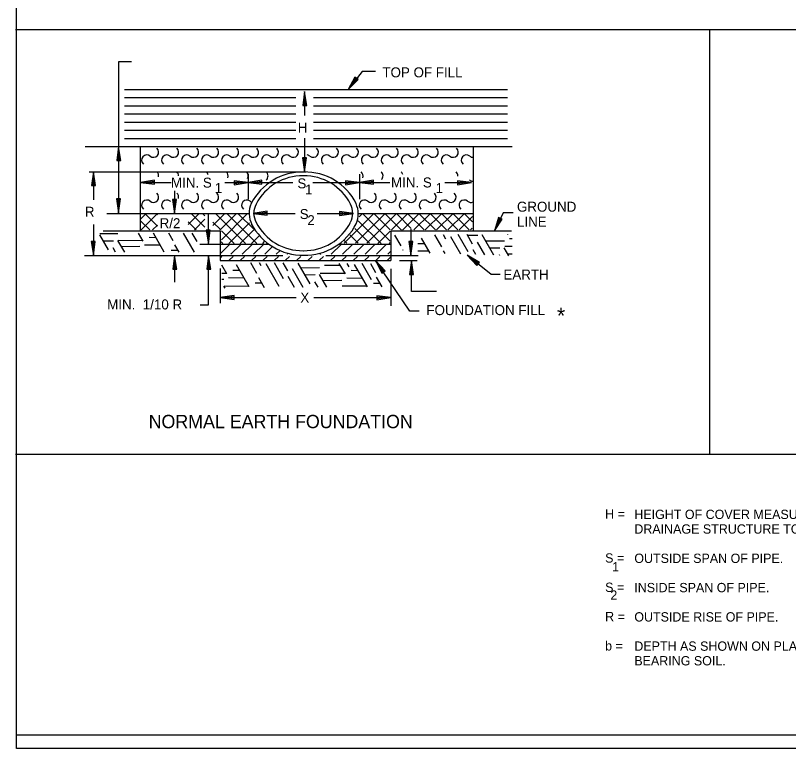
# Model space of a CAD drawing. Extents: x 0 to 390, y 0 to 265.
# Drawn here: x -0.2 to 144.9, y 0 to 137.7 of the extents above; entities that cross this region are included whole.
import ezdxf

# ---------------------------------------------------------------- set-up
doc = ezdxf.new("R2010")
doc.units = 0
doc.layers.add('D_Details', color=7, linetype='Continuous')
doc.layers.add('Default', color=7, linetype='Continuous')

msp = doc.modelspace()

# ---------------------------------------------------------------- linework, layer by layer
at = {"layer": 'D_Details'}
for p, q in [((-0.22, 135.01), (388.66, 135.01)), ((130.04, 135.01), (130.04, 55.26)), ((21.55, 128.98), (19.13, 128.98)), ((19.13, 128.98), (19.13, 113.05)), ((64.85, 127.14), (62.23, 123.76)), ((67.36, 127.14), (64.85, 127.14)), ((63.51, 126.09), (62.23, 123.76)), ((62.23, 123.76), (64.1, 125.63)), ((62.63, 124.28), (63.66, 125.97)), ((63.95, 125.74), (62.63, 124.28)), ((63.25, 125.11), (63.73, 125.92)), ((63.88, 125.8), (63.25, 125.11)), ((64.1, 125.63), (63.51, 126.09)), ((20.23, 123.76), (92.15, 123.76)), ((54.05, 123.38), (53.71, 120.75)), ((54.46, 120.75), (54.05, 123.38)), ((54.05, 123.38), (54.05, 118.89)), ((20.23, 122.23), (52.42, 122.23)), ((53.9, 120.75), (54.05, 122.72)), ((54.05, 122.72), (54.27, 120.75)), ((55.72, 122.23), (92.15, 122.23)), ((20.23, 120.7), (52.42, 120.7)), ((53.71, 120.75), (54.46, 120.75)), ((53.99, 120.75), (54.07, 121.69)), ((54.07, 121.69), (54.18, 120.75)), ((55.72, 120.7), (92.15, 120.7)), ((20.23, 119.17), (52.42, 119.17)), ((55.72, 119.17), (92.15, 119.17)), ((20.23, 117.64), (52.42, 117.64)), ((55.72, 117.64), (92.15, 117.64)), ((20.23, 116.11), (52.42, 116.11)), ((55.72, 116.11), (92.15, 116.11)), ((20.23, 114.58), (52.42, 114.58)), ((54.05, 114.59), (54.05, 108.32)), ((55.72, 114.58), (92.15, 114.58)), ((12.87, 113.05), (93.01, 113.05)), ((19.14, 113.05), (18.8, 110.43)), ((18.99, 110.43), (19.14, 112.39)), ((19.13, 113.05), (19.13, 100.6)), ((19.55, 110.43), (19.14, 113.05)), ((19.14, 112.39), (19.36, 110.43)), ((23.19, 112.95), (23.19, 97.22)), ((85.68, 112.86), (85.68, 97.22)), ((18.8, 110.43), (19.55, 110.43)), ((19.08, 110.43), (19.15, 111.36)), ((19.15, 111.36), (19.27, 110.43)), ((54.39, 110.94), (53.64, 110.94)), ((53.64, 110.94), (54.05, 108.32)), ((54.05, 108.98), (53.82, 110.94)), ((54.03, 110.01), (53.92, 110.94)), ((54.1, 110.94), (54.03, 110.01)), ((54.05, 108.32), (54.39, 110.94)), ((54.2, 110.94), (54.05, 108.98)), ((13.64, 108.32), (54.34, 108.32)), ((14.41, 108.32), (14.07, 105.7)), ((14.26, 105.7), (14.41, 107.66)), ((14.82, 105.7), (14.41, 108.32)), ((14.41, 108.32), (14.41, 103.03)), ((14.41, 107.66), (14.63, 105.7)), ((43.44, 107.93), (43.44, 103.16)), ((64.37, 107.84), (64.37, 103.16)), ((14.35, 105.7), (14.43, 106.63)), ((14.43, 106.63), (14.54, 105.7)), ((25.91, 106.71), (23.28, 106.29)), ((23.28, 106.29), (25.91, 105.96)), ((23.28, 106.29), (29, 106.29)), ((23.94, 106.29), (25.91, 106.52)), ((25.91, 106.14), (23.94, 106.29)), ((24.97, 106.31), (25.91, 106.42)), ((25.91, 106.24), (24.97, 106.31)), ((25.91, 105.96), (25.91, 106.71)), ((39.07, 106.29), (43.44, 106.29)), ((43.44, 106.29), (40.82, 106.63)), ((40.82, 106.63), (40.82, 105.88)), ((40.82, 106.44), (42.78, 106.29)), ((40.82, 106.35), (41.75, 106.27)), ((40.82, 105.88), (43.44, 106.29)), ((42.78, 106.29), (40.82, 106.07)), ((41.75, 106.27), (40.82, 106.16)), ((46.06, 106.71), (43.44, 106.29)), ((43.44, 106.29), (46.06, 105.96)), ((43.44, 106.29), (51.84, 106.29)), ((44.1, 106.29), (46.06, 106.52)), ((46.06, 106.14), (44.1, 106.29)), ((45.13, 106.31), (46.06, 106.42)), ((46.06, 106.24), (45.13, 106.31)), ((46.06, 105.96), (46.06, 106.71)), ((55.58, 106.29), (64.37, 106.29)), ((64.37, 106.29), (61.74, 106.63)), ((61.74, 106.63), (61.74, 105.88)), ((61.74, 106.44), (63.71, 106.29)), ((61.74, 106.35), (62.68, 106.27)), ((61.74, 105.88), (64.37, 106.29)), ((63.71, 106.29), (61.74, 106.07)), ((62.68, 106.27), (61.74, 106.16)), ((66.99, 106.71), (64.37, 106.29)), ((64.37, 106.29), (66.99, 105.96)), ((64.37, 106.29), (70.04, 106.29)), ((65.02, 106.29), (66.99, 106.52)), ((66.99, 106.14), (65.02, 106.29)), ((66.06, 106.31), (66.99, 106.42)), ((66.99, 106.24), (66.06, 106.31)), ((66.99, 105.96), (66.99, 106.71)), ((80.36, 106.29), (85.39, 106.29)), ((85.39, 106.29), (82.77, 106.63)), ((82.77, 106.63), (82.77, 105.88)), ((82.77, 106.44), (84.74, 106.29)), ((82.77, 106.35), (83.71, 106.27)), ((82.77, 105.88), (85.39, 106.29)), ((84.74, 106.29), (82.77, 106.07)), ((83.71, 106.27), (82.77, 106.16)), ((14.07, 105.7), (14.82, 105.7)), ((29.65, 104.75), (29.65, 100.5)), ((19.47, 103.22), (18.72, 103.22)), ((18.72, 103.22), (19.14, 100.6)), ((19.14, 101.25), (18.91, 103.22)), ((19.12, 102.29), (19, 103.22)), ((19.19, 103.22), (19.12, 102.29)), ((19.14, 100.6), (19.47, 103.22)), ((19.29, 103.22), (19.14, 101.25)), ((29.99, 103.13), (29.24, 103.13)), ((29.24, 103.13), (29.65, 100.5)), ((29.65, 101.16), (29.42, 103.13)), ((29.63, 102.19), (29.52, 103.13)), ((29.7, 103.13), (29.63, 102.19)), ((29.65, 100.5), (29.99, 103.13)), ((29.8, 103.13), (29.65, 101.16)), ((16.92, 100.5), (43.65, 100.5)), ((23.28, 99.4), (24.27, 100.39)), ((23.39, 97.38), (26.35, 100.35)), ((26.43, 98.08), (24.12, 100.39)), ((26.43, 100.2), (26.29, 100.35)), ((32.23, 98.41), (34.17, 100.35)), ((35.32, 97.92), (32.89, 100.35)), ((35.32, 100.04), (35.01, 100.35)), ((36.01, 94.71), (36.01, 100.5)), ((36.83, 98.19), (39.02, 100.39)), ((36.87, 100.35), (36.92, 100.41)), ((42.96, 94.85), (37.4, 100.4)), ((38.13, 97.37), (41.13, 100.37)), ((38.43, 95.55), (43.23, 100.35)), ((45.08, 94.85), (39.54, 100.38)), ((44.45, 97.6), (41.68, 100.36)), ((47.06, 100.91), (44.43, 100.5)), ((44.43, 100.5), (52.27, 100.5)), ((44.43, 100.5), (47.06, 100.16)), ((45.09, 100.5), (47.06, 100.73)), ((47.06, 100.35), (45.09, 100.5)), ((46.12, 100.52), (47.06, 100.63)), ((47.06, 100.45), (46.12, 100.52)), ((47.06, 100.16), (47.06, 100.91)), ((56.44, 100.5), (63.21, 100.5)), ((63.21, 100.5), (60.58, 100.84)), ((60.58, 100.84), (60.58, 100.09)), ((60.58, 100.65), (62.55, 100.5)), ((60.58, 100.56), (61.52, 100.48)), ((60.58, 100.09), (63.21, 100.5)), ((62.55, 100.5), (60.58, 100.28)), ((61.52, 100.48), (60.58, 100.37)), ((61.51, 94.91), (67.01, 100.41)), ((63.62, 94.89), (69.13, 100.41)), ((64.14, 100.5), (85.68, 100.5)), ((64.33, 99.85), (64.89, 100.41)), ((70.1, 95.28), (64.97, 100.41)), ((65.72, 94.88), (71.25, 100.41)), ((70.1, 97.4), (67.09, 100.41)), ((72.25, 97.37), (69.21, 100.41)), ((70.4, 97.43), (73.37, 100.41)), ((74.08, 97.66), (71.34, 100.41)), ((72.45, 97.37), (75.49, 100.41)), ((76.48, 97.38), (73.46, 100.41)), ((74.59, 97.38), (77.62, 100.41)), ((78.6, 97.38), (75.58, 100.41)), ((76.71, 97.38), (79.74, 100.41)), ((80.72, 97.38), (77.7, 100.41)), ((78.83, 97.38), (81.86, 100.41)), ((82.84, 97.38), (79.82, 100.41)), ((80.95, 97.38), (83.98, 100.41)), ((84.97, 97.38), (81.94, 100.41)), ((85.56, 98.91), (84.06, 100.41)), ((91.36, 100.59), (89.68, 97.22)), ((93.23, 100.59), (91.36, 100.59)), ((25.01, 97.38), (23.28, 99.11)), ((33.7, 97.41), (32.23, 98.88)), ((33.36, 97.42), (35.32, 99.38)), ((38.31, 97.38), (36.84, 98.85)), ((39.85, 94.85), (43.71, 98.71)), ((68.4, 94.86), (64.14, 99.12)), ((83.07, 97.38), (85.58, 99.89)), ((90.48, 99.75), (89.68, 97.22)), ((89.68, 97.22), (91.15, 99.42)), ((89.97, 97.81), (90.65, 99.67)), ((90.98, 99.5), (89.97, 97.81)), ((90.41, 98.74), (90.73, 99.63)), ((90.9, 99.54), (90.41, 98.74)), ((91.15, 99.42), (90.48, 99.75)), ((14.41, 98.43), (14.41, 92.61)), ((25.51, 97.38), (26.43, 98.31)), ((36.35, 97.34), (35.6, 97.34)), ((35.6, 97.34), (36.01, 94.71)), ((36.35, 97.34), (35.6, 97.34)), ((35.6, 97.34), (36.01, 94.71)), ((36.01, 95.37), (35.79, 97.34)), ((36.01, 95.37), (35.79, 97.34)), ((35.99, 96.4), (35.88, 97.34)), ((35.99, 96.4), (35.88, 97.34)), ((36.07, 97.34), (35.99, 96.4)), ((36.07, 97.34), (35.99, 96.4)), ((36.01, 94.71), (36.35, 97.34)), ((36.16, 97.34), (36.01, 95.37)), ((36.01, 94.71), (36.35, 97.34)), ((36.16, 97.34), (36.01, 95.37)), ((41.97, 94.85), (44.56, 97.44)), ((66.26, 94.87), (63.49, 97.65)), ((74.01, 97.51), (74.01, 92.61)), ((74.36, 97.38), (74.36, 97.39)), ((85.19, 97.38), (85.54, 97.72)), ((18.97, 96.66), (15.63, 96.65)), ((17.25, 93.67), (15.65, 96.44)), ((16.24, 97.22), (38.23, 97.22)), ((23.74, 95.29), (22.9, 96.75)), ((26.16, 95.93), (24.87, 95.94)), ((27.72, 93.21), (25.68, 96.75)), ((29.37, 95.35), (28.56, 96.75)), ((33.38, 93.21), (31.35, 96.75)), ((33.87, 95.2), (32.98, 96.75)), ((38.23, 97.22), (38.23, 91.62)), ((40.84, 94.85), (38.47, 97.21)), ((44.09, 94.85), (45.48, 96.24)), ((64.13, 94.89), (62.55, 96.47)), ((67.83, 94.86), (70.1, 97.13)), ((70.25, 97.22), (70.25, 91.62)), ((70.25, 97.22), (92.92, 97.22)), ((72.16, 94.43), (71.02, 96.4)), ((77.6, 93.02), (75.98, 95.83)), ((79.8, 94.2), (78.51, 96.45)), ((80.59, 95.65), (80.13, 96.47)), ((83.37, 92.84), (81.5, 96.08)), ((84.76, 93.25), (82.9, 96.5)), ((85.6, 94.71), (84.55, 96.53)), ((86.56, 96.36), (84.73, 96.34)), ((89.58, 92.64), (87.37, 96.46)), ((92.23, 96.55), (92.19, 96.62)), ((14.75, 95.24), (14, 95.24)), ((14, 95.24), (14.41, 92.61)), ((14.41, 93.27), (14.18, 95.24)), ((14.39, 94.3), (14.28, 95.24)), ((14.47, 95.24), (14.39, 94.3)), ((14.41, 92.61), (14.75, 95.24)), ((14.56, 95.24), (14.41, 93.27)), ((18.19, 95.3), (16.32, 95.29)), ((20.29, 93.21), (19.01, 95.42)), ((23.69, 95.36), (19.04, 95.41)), ((26.9, 94.51), (24.01, 94.53)), ((30.5, 93.21), (29.72, 94.57)), ((34.37, 94.71), (47.29, 94.71)), ((38.27, 92.98), (39.95, 94.66)), ((38.71, 94.85), (38.42, 95.14)), ((40.22, 92.81), (42.08, 94.67)), ((42.34, 92.81), (44.2, 94.67)), ((44.46, 92.81), (46.33, 94.68)), ((46.21, 94.85), (46.55, 95.19)), ((59.06, 92.81), (60.93, 94.67)), ((60.48, 94.71), (70.25, 94.71)), ((61.18, 92.81), (63.04, 94.66)), ((61.99, 94.9), (61.47, 95.43)), ((63.3, 92.81), (65.15, 94.65)), ((65.43, 92.81), (67.26, 94.64)), ((67.55, 92.81), (69.37, 94.63)), ((69.94, 94.85), (70.1, 95.01)), ((74.35, 95.24), (73.6, 95.24)), ((73.6, 95.24), (74.01, 92.61)), ((74.01, 93.27), (73.79, 95.24)), ((73.99, 94.3), (73.88, 95.24)), ((74.07, 95.24), (73.99, 94.3)), ((74.01, 92.61), (74.35, 95.24)), ((74.16, 95.24), (74.01, 93.27)), ((76.59, 94.79), (75.3, 94.8)), ((87.87, 92.69), (86.5, 95.1)), ((91.55, 95.3), (88.1, 95.26)), ((93.04, 95.74), (92.51, 95.74)), ((18.56, 93.21), (18.1, 94)), ((23.14, 94.25), (19.71, 94.24)), ((30.32, 93.53), (29.03, 93.54)), ((46.58, 92.81), (47.98, 94.21)), ((48.7, 92.81), (49.38, 93.49)), ((50.82, 92.81), (50.94, 92.93)), ((56.94, 92.81), (57.1, 92.97)), ((69.67, 92.81), (70.19, 93.34)), ((72.58, 93.53), (72.5, 93.66)), ((77.33, 93.37), (75.32, 93.38)), ((80.43, 92.93), (80.15, 93.43)), ((86.2, 92.75), (85.67, 93.67)), ((90.73, 93.96), (88.89, 93.93)), ((92.41, 92.54), (91.53, 94.05)), ((93.04, 94.25), (91.65, 94.25)), ((12.76, 92.61), (49.95, 92.61)), ((29.65, 92.61), (29.31, 89.99)), ((29.5, 89.99), (29.65, 91.96)), ((29.65, 92.61), (29.65, 87.57)), ((30.06, 89.99), (29.65, 92.61)), ((29.65, 91.96), (29.87, 89.99)), ((36.01, 92.61), (35.68, 89.99)), ((35.86, 89.99), (36.01, 91.96)), ((36.01, 83.32), (36.01, 92.61)), ((36.43, 89.99), (36.01, 92.61)), ((36.01, 91.96), (36.24, 89.99)), ((38.23, 91.62), (70.25, 91.62)), ((38.31, 92.21), (38.52, 92.42)), ((39.9, 91.68), (40.64, 92.42)), ((42.02, 91.68), (42.76, 92.42)), ((44.14, 91.68), (44.89, 92.42)), ((46.26, 91.68), (47.01, 92.42)), ((48.38, 91.68), (49.13, 92.42)), ((50.5, 91.68), (51.25, 92.42)), ((52.62, 91.68), (53.37, 92.42)), ((54.74, 91.68), (55.49, 92.42)), ((56.86, 91.68), (57.61, 92.42)), ((58.07, 92.61), (75.36, 92.61)), ((58.98, 91.68), (59.73, 92.42)), ((61.1, 91.68), (61.85, 92.42)), ((63.22, 91.68), (63.97, 92.42)), ((65.35, 91.68), (66.09, 92.42)), ((73.82, 82.16), (67.35, 91.62)), ((67.35, 91.62), (68.55, 89.27)), ((69.17, 89.69), (67.35, 91.62)), ((67.47, 91.68), (68.21, 92.42)), ((69.59, 91.68), (70.17, 92.26)), ((71.9, 91.62), (75.17, 91.62)), ((74.11, 91.62), (73.77, 89)), ((74.11, 85.83), (74.11, 91.62)), ((74.52, 89), (74.11, 91.62)), ((89.05, 88.99), (84.6, 92.64)), ((84.6, 92.64), (86.41, 90.71)), ((86.89, 91.29), (84.6, 92.64)), ((86.53, 90.86), (85.11, 92.22)), ((85.11, 92.22), (86.77, 91.15)), ((86.59, 90.93), (85.91, 91.58)), ((85.91, 91.58), (86.71, 91.07)), ((90.72, 92.6), (90.66, 92.7)), ((93.04, 92.86), (92.27, 92.85)), ((29.31, 89.99), (30.06, 89.99)), ((29.59, 89.99), (29.67, 90.92)), ((29.67, 90.92), (29.78, 89.99)), ((35.68, 89.99), (36.43, 89.99)), ((35.96, 89.99), (36.03, 90.92)), ((36.03, 90.92), (36.14, 89.99)), ((38.23, 90.13), (38.23, 83.61)), ((39.49, 89.13), (38.54, 90.76)), ((43.65, 86.72), (41.29, 90.81)), ((45.12, 89.18), (43.94, 91.23)), ((45.91, 90.63), (45.57, 91.21)), ((49.28, 86.77), (46.82, 91.05)), ((50.07, 88.22), (48.38, 91.19)), ((50.92, 89.68), (50.05, 91.18)), ((53.8, 86.59), (51.81, 90.08)), ((55.08, 87.28), (52.84, 91.15)), ((56.86, 90.28), (53.41, 90.23)), ((60.71, 90.7), (57.82, 90.72)), ((61.71, 89.13), (60.55, 91.09)), ((62.42, 90.44), (62.05, 91.08)), ((65.87, 86.72), (63.4, 90.92)), ((66.59, 88.04), (64.84, 91.06)), ((67.44, 89.36), (66.46, 91.05)), ((68.71, 89.37), (67.72, 91.08)), ((67.72, 91.08), (69.02, 89.58)), ((68.78, 89.42), (68.32, 90.24)), ((68.32, 90.24), (68.94, 89.53)), ((70.25, 90.06), (70.25, 83.13)), ((73.96, 89), (74.11, 90.97)), ((74.11, 90.97), (74.33, 89)), ((86.41, 90.71), (86.89, 91.29)), ((39.44, 89.2), (38.54, 89.2)), ((41.9, 89.77), (40.61, 89.78)), ((52.18, 86.58), (50.98, 88.65)), ((56.04, 88.93), (54.21, 88.91)), ((58.24, 86.62), (56.85, 89.03)), ((61.63, 89.21), (56.96, 89.23)), ((64.11, 89.73), (62.81, 89.74)), ((68.55, 89.27), (69.17, 89.69)), ((73.77, 89), (74.52, 89)), ((74.05, 89), (74.13, 89.93)), ((74.13, 89.93), (74.24, 89)), ((90.76, 88.99), (89.05, 88.99)), ((38.89, 88.09), (38.54, 88.09)), ((42.64, 88.34), (39.75, 88.37)), ((46.07, 87.36), (44.78, 87.37)), ((46.54, 86.54), (45.46, 88.4)), ((56.58, 86.61), (55.98, 87.67)), ((61.03, 87.87), (57.58, 87.83)), ((64.88, 88.29), (61.99, 88.31)), ((68.27, 87.33), (66.98, 87.34)), ((68.64, 86.7), (67.57, 88.51)), ((39.14, 86.48), (38.92, 86.85)), ((43.61, 86.79), (38.96, 86.83)), ((65.8, 86.81), (61.13, 86.82)), ((78.84, 85.83), (74.11, 85.83)), ((40.86, 85.08), (38.23, 84.67)), ((38.23, 84.67), (40.86, 84.33)), ((38.23, 84.67), (52.47, 84.67)), ((38.89, 84.67), (40.86, 84.9)), ((40.86, 84.52), (38.89, 84.67)), ((39.92, 84.69), (40.86, 84.8)), ((40.86, 84.62), (39.92, 84.69)), ((40.86, 84.33), (40.86, 85.08)), ((55.81, 84.67), (70.25, 84.67)), ((70.25, 84.67), (67.63, 85.01)), ((67.63, 85.01), (67.63, 84.26)), ((67.63, 84.82), (69.6, 84.67)), ((67.63, 84.73), (68.56, 84.65)), ((67.63, 84.26), (70.25, 84.67)), ((69.6, 84.67), (67.63, 84.45)), ((68.56, 84.65), (67.63, 84.54)), ((34.47, 83.32), (36.01, 83.32)), ((75.56, 82.16), (73.82, 82.16)), ((-0.22, 55.26), (389.68, 55.26))]:
    msp.add_line(p, q, dxfattribs=at)
for centre, radius, start, end in [((25.69, 111.99), 0.975, 230, 50), ((29.44, 111.99), 0.975, 230, 50), ((33.19, 111.99), 0.975, 230, 50), ((36.94, 111.99), 0.975, 230, 50), ((40.69, 111.99), 0.975, 230, 50), ((44.44, 111.99), 0.975, 230, 50), ((48.19, 111.99), 0.975, 230, 50), ((51.94, 111.99), 0.975, 230, 50), ((55.69, 111.99), 0.975, 230, 50), ((59.44, 111.99), 0.975, 230, 50), ((63.19, 111.99), 0.975, 230, 50), ((66.93, 111.99), 0.975, 230, 50), ((70.68, 111.99), 0.975, 230, 50), ((74.43, 111.99), 0.975, 230, 50), ((78.18, 111.99), 0.975, 230, 50), ((81.93, 111.99), 0.975, 230, 50), ((24.44, 110.5), 0.975, 50, 230), ((28.19, 110.5), 0.975, 50, 230), ((31.94, 110.5), 0.975, 50, 230), ((35.69, 110.5), 0.975, 50, 230), ((39.44, 110.5), 0.975, 50, 230), ((43.19, 110.5), 0.975, 50, 230), ((46.94, 110.5), 0.975, 50, 230), ((50.68, 110.5), 0.975, 50, 230), ((54.43, 110.5), 0.975, 50, 82.3266), ((58.18, 110.5), 0.975, 50, 230), ((61.93, 110.5), 0.975, 50, 230), ((65.68, 110.5), 0.975, 50, 230), ((69.43, 110.5), 0.975, 50, 230), ((73.18, 110.5), 0.975, 50, 230), ((76.93, 110.5), 0.975, 50, 230), ((80.68, 110.5), 0.975, 50, 230), ((84.43, 110.5), 0.975, 50, 230), ((85.68, 111.99), 0.975, 230, 270.2239), ((25.69, 107.54), 0.975, 349.1607, 50), ((29.44, 107.54), 0.975, 0.3195, 50), ((34.98, 107.54), 0.975, 9.9527, 50), ((38.73, 107.54), 0.975, 339.3999, 50), ((42.48, 107.54), 0.975, 328.9926, 50), ((53.72, 97.42), 10.85, 89.0105, 152.9614), ((53.65, 97.78), 9.77, 89.0105, 152.9614), ((46.23, 107.54), 0.975, 309.7167, 50), ((53.99, 97.78), 9.77, 27.0239, 90.9895), ((54.09, 97.42), 10.85, 27.0239, 90.9895), ((64.06, 107.54), 0.975, 338.4469, 50), ((67.8, 107.54), 0.975, 314.2231, 50), ((71.55, 107.54), 0.975, 15.7166, 50), ((81.87, 107.54), 0.975, 357.5745, 50), ((85.61, 107.54), 0.975, 230, 274.0281), ((25.69, 103.53), 0.975, 230, 50), ((29.44, 103.53), 0.975, 345.4383, 50), ((33.19, 103.53), 0.975, 230, 50), ((36.94, 103.53), 0.975, 230, 50), ((40.69, 103.53), 0.975, 230, 50), ((66.54, 103.53), 0.975, 230, 50), ((70.29, 103.53), 0.975, 230, 50), ((74.04, 103.53), 0.975, 230, 50), ((77.79, 103.53), 0.975, 230, 50), ((81.53, 103.53), 0.975, 230, 50), ((24.44, 102.03), 0.975, 50, 230), ((28.19, 102.03), 0.975, 50, 230), ((29.44, 103.53), 0.975, 230, 234.4516), ((31.94, 102.03), 0.975, 50, 230), ((35.69, 102.03), 0.975, 50, 230), ((39.44, 102.03), 0.975, 50, 230), ((43.19, 102.03), 0.975, 50, 230), ((48.24, 100.48), 4.59, 155.8288, 206.9141), ((44.44, 103.53), 0.975, 230, 253.5225), ((48.15, 100.52), 3.62, 151.971, 208.2086), ((59.28, 100.48), 3.79, 333.921, 27.1329), ((59.55, 100.38), 4.59, 336.5469, 25.086), ((65.28, 102.03), 0.975, 50, 230), ((69.03, 102.03), 0.975, 50, 230), ((72.78, 102.03), 0.975, 50, 230), ((76.53, 102.03), 0.975, 50, 230), ((80.28, 102.03), 0.975, 50, 230), ((84.03, 102.03), 0.975, 50, 230), ((85.28, 103.53), 0.975, 230, 294.211), ((53.65, 103.25), 9.77, 207.0386, 270.9895), ((53.99, 103.25), 9.77, 269.0105, 332.9761), ((53.72, 103.49), 10.85, 207.0386, 270.9895), ((54.09, 103.49), 10.85, 269.0105, 332.9761)]:
    msp.add_arc(centre, radius, start, end, dxfattribs=at)
at = {"layer": 'Default'}
for points in [[(0, 265), (326.25, 265), (326.25, 255), (390, 255), (390, 37.5), (315, 37.5), (315, 0), (0, 0)], [(0, 262.5), (326.25, 262.5), (326.25, 252.5), (390, 252.5), (390, 40), (315, 40), (315, 2.5), (0, 2.5)]]:
    msp.add_lwpolyline(points, close=True, dxfattribs=at)

# ---------------------------------------------------------------- texts
at = {"layer": 'D_Details'}
for s, height, p in [('TOP OF FILL', 1.8745, (68.66, 126.04)), ('H', 1.87, (52.78, 115.68)), ('MIN. S', 1.875, (28.97, 105.33)), ('1', 1.87, (37.19, 104.32)), ('S', 1.87, (52.71, 105.19)), ('MIN. S ', 1.875, (70.27, 105.36)), ('1', 1.87, (78.64, 104.32)), ('1', 1.87, (54.14, 104.04)), ('R', 1.87, (12.81, 99.87)), ('GROUND', 1.875, (93.92, 100.81)), ('S', 1.87, (53.14, 99.43)), ('2', 1.87, (54.57, 98.28)), ('R/2', 1.875, (26.84, 97.71)), ('LINE', 1.875, (93.92, 97.99)), ('EARTH', 1.875, (91.38, 88.07)), ('MIN.  1/10 R', 1.8745, (17, 82.46)), ('X', 1.87, (53.26, 83.74)), ('FOUNDATION FILL ', 1.8745, (76.92, 81.39)), ('*', 3, (101.42, 79.78)), ('NORMAL EARTH FOUNDATION', 2.4994, (24.78, 60.16)), ('H = ', 1.75, (110.47, 43.16)), ('HEIGHT OF COVER MEASURED FROM TOP OF', 1.7496, (115.95, 43.1)), ('DRAINAGE STRUCTURE TO FINISHED GRADE.', 1.7496, (115.95, 40.35)), ('S = ', 1.75, (110.47, 34.91)), ('OUTSIDE SPAN OF PIPE.', 1.7496, (115.95, 34.85)), ('1', 1.75, (111.79, 33.26)), ('S = ', 1.75, (110.47, 29.41)), ('INSIDE SPAN OF PIPE.', 1.7496, (115.95, 29.35)), ('2', 1.75, (111.45, 27.93)), ('R = ', 1.75, (110.47, 23.91)), ('OUTSIDE RISE OF PIPE.', 1.7496, (115.95, 23.85)), ('b = ', 1.75, (110.47, 18.41)), ('DEPTH AS SHOWN ON PLANS OR TO FIRM', 1.7496, (115.95, 18.36)), ('BEARING SOIL.', 1.7496, (115.95, 15.61))]:
    msp.add_text(s, height=height, dxfattribs=at).set_placement(p)

doc.saveas('drawing.dxf')
